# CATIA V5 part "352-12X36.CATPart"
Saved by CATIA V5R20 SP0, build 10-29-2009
Part number: 352-12X36
Definition: NONE
Nomenclature: 352-12X36
Source: Unknown
Description: 352-12X36
Bounding box of the stored display mesh (mm): x 0 to 36, y -9 to 9, z -9 to 9
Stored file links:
  C:\Users\Utente\Desktop\IO LAVORO\3D X SITO CF\X SITO\PLASTICA\352\352-12X36.CATPart
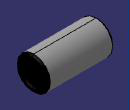
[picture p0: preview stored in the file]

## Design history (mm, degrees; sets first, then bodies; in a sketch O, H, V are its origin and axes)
Body1 "352-12X36" (main body)
  Solid1: solid without history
